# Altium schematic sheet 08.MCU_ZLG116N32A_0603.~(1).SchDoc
size A4; CheckedBy: <审核日期>; Author: 伍伟业; CompanyName: 广州周立功单片机科技有限公司; DocumentNumber: 7; SheetNumber: 7; SheetTotal: 7; PageSetup: Record=PageOptions¦CenterHorizontal=True¦CenterVertical=True¦PrintScale=1.00¦XCorrection=1.00¦YCorrection=1.00¦PrintKind=0¦BorderSize=5000000¦LeftOffset=0¦BottomOffset=0¦Orientation=2¦PaperLength=1000¦PaperWidth=1000¦Scale=100¦PaperSource=7¦PrintQuality=600¦MediaType=1¦DitherType=10¦PaperKind=A4¦PrintScaleMode=1; DesignDate: 2016-8-4; CheckDate: 赵金生; SheetName: MCU_ZLG116N32A; SheetVersion: Rev.A; SheetDescription: ZLG116N32A最小系统
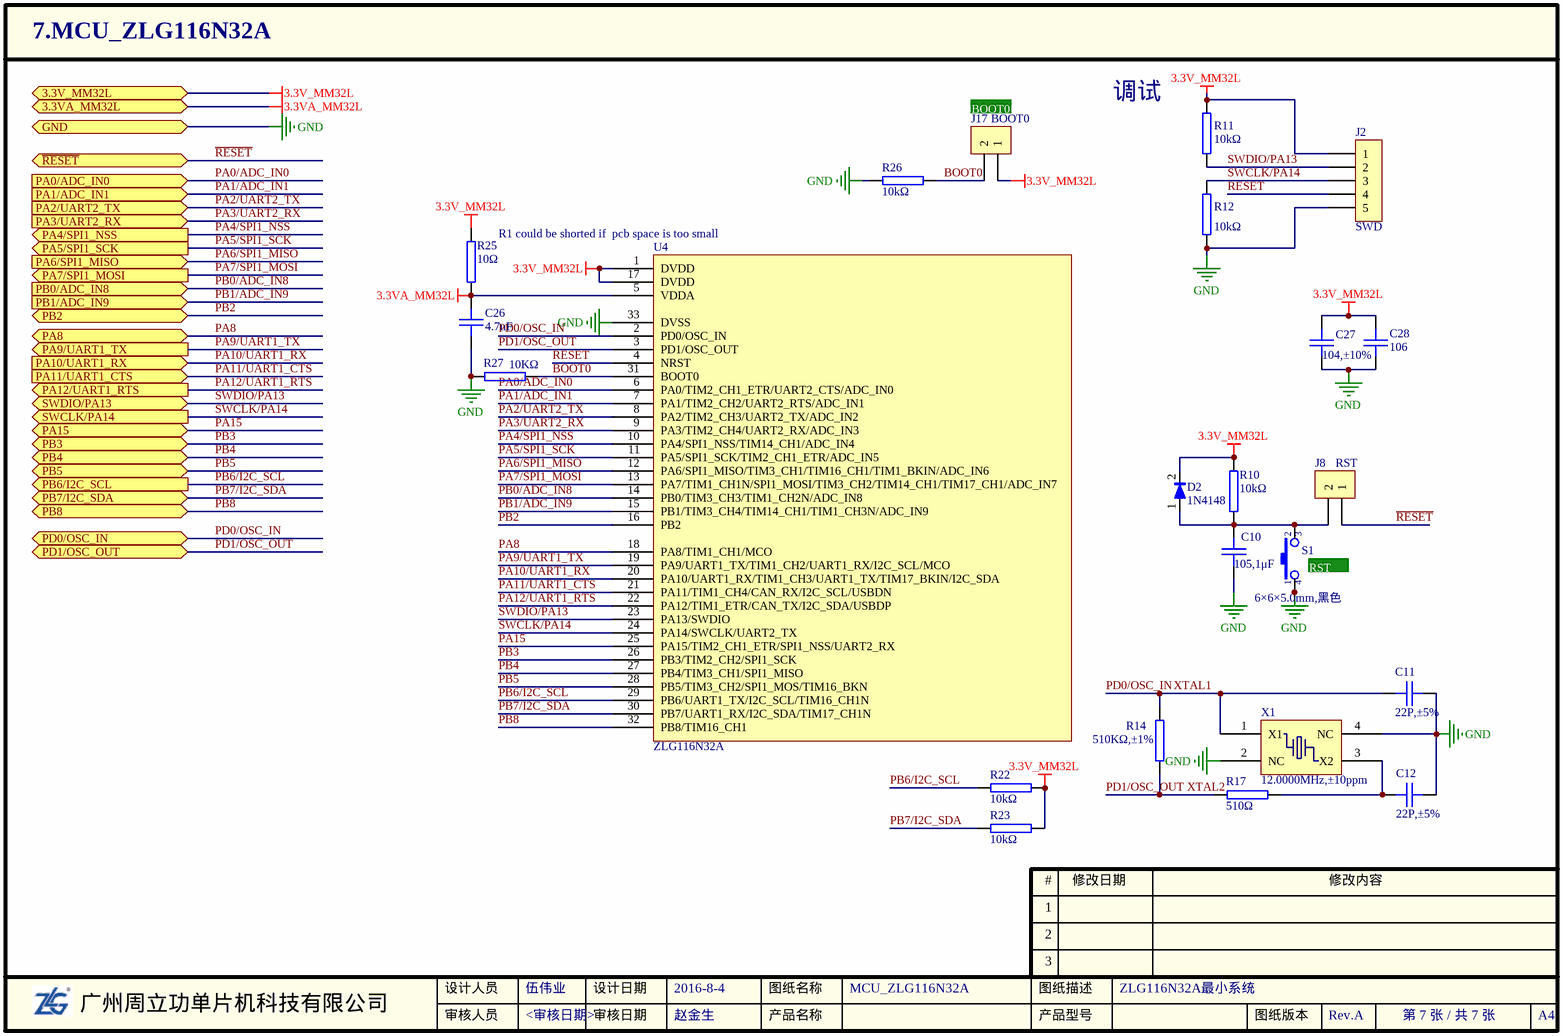
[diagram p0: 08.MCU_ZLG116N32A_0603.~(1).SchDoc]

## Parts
C10  105,1μF  [0603C]
C11  22P,±5%  [0603C]
C12  22P,±5%  [0603C]
C26  4.7uF  [0603C]
C27  104,±10%  [0603C]
C28  106  [0805C]
D2  value 1N4148  [SOD-323]  (hidden comment: DIODE1)
J2  SWD  [SIP-5-2.54-R90]
J8  RST  [SIP-2-2.54]
J17  BOOT0  [SIP-2-2.54]
R10  10kΩ  [0603R]
R11  10kΩ  [0603R]
R12  10kΩ  [0603R]
R14  510KΩ,±1%  [禁止选用0603R]
R17  510Ω  [0603R]
R22  10kΩ  [0603R]
R23  10kΩ  [0603R]
R25  10Ω  [0603R]
R26  10kΩ  [0603R]
R27  10KΩ  [0603R]
S1  value 6×6×5.0mm,黑色  [KEY-6S]  (hidden comment: RST)
U4  ZLG116N32A  [QFN50P500X500X85-33N]
X1  12.0000MHz,±10ppm  [XTAL4-3.2X2.5]

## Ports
3.3V_MM32L, 3.3VA_MM32L, GND, PA0/ADC_IN0 (in), PA1/ADC_IN1 (in), PA2/UART2_TX (in), PA3/UART2_RX (in), PA4/SPI1_NSS (out), PA5/SPI1_SCK (out), PA6/SPI1_MISO (in), PA7/SPI1_MOSI (out), PA8 (bidir), PA9/UART1_TX (out), PA10/UART1_RX (in), PA11/UART1_CTS (in), PA12/UART1_RTS (out), PA15 (bidir), PB0/ADC_IN8 (in), PB1/ADC_IN9 (in), PB2 (bidir), PB3 (bidir), PB4 (bidir), PB5 (bidir), PB6/I2C_SCL (out), PB7/I2C_SDA (bidir), PB8 (bidir), PD0/OSC_IN (bidir), PD1/OSC_OUT (bidir), SWCLK/PA14 (out), SWDIO/PA13 (bidir), ~{RESET} (bidir)

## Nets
3.3V_MM32L: C27.1 C28.1 D2.2 J2.1 J17.1 R10.2 R11.2 R22.2 R23.2 R25.2 U4.1(DVDD) U4.17(DVDD) ; port 3.3V_MM32L
3.3VA_MM32L: C26.1 R25.1 U4.5(VDDA) ; port 3.3VA_MM32L
GND: C10.2 C11.2 C12.2 C26.2 C27.2 C28.2 J2.5 R12.1 R26.1 R27.1 S1.1 S1.4 U4.33(DVSS) X1.2(NC) X1.4(NC) ; port GND
BOOT0: J17.2 R26.2 R27.2 U4.31(BOOT0)
PA0/ADC_IN0: U4.6(PA0/TIM2_CH1_ETR/UART2_CTS/ADC_IN0) ; port PA0/ADC_IN0
PA1/ADC_IN1: U4.7(PA1/TIM2_CH2/UART2_RTS/ADC_IN1) ; port PA1/ADC_IN1
PA2/UART2_TX: U4.8(PA2/TIM2_CH3/UART2_TX/ADC_IN2) ; port PA2/UART2_TX
PA3/UART2_RX: U4.9(PA3/TIM2_CH4/UART2_RX/ADC_IN3) ; port PA3/UART2_RX
PA4/SPI1_NSS: U4.10(PA4/SPI1_NSS/TIM14_CH1/ADC_IN4) ; port PA4/SPI1_NSS
PA5/SPI1_SCK: U4.11(PA5/SPI1_SCK/TIM2_CH1_ETR/ADC_IN5) ; port PA5/SPI1_SCK
PA6/SPI1_MISO: U4.12(PA6/SPI1_MISO/TIM3_CH1/TIM16_CH1/TIM1_BKIN/ADC_IN6) ; port PA6/SPI1_MISO
PA7/SPI1_MOSI: U4.13(PA7/TIM1_CH1N/SPI1_MOSI/TIM3_CH2/TIM14_CH1/TIM17_CH1/ADC_IN7) ; port PA7/SPI1_MOSI
PA8: U4.18(PA8/TIM1_CH1/MCO) ; port PA8
PA9/UART1_TX: U4.19(PA9/UART1_TX/TIM1_CH2/UART1_RX/I2C_SCL/MCO) ; port PA9/UART1_TX
PA10/UART1_RX: U4.20(PA10/UART1_RX/TIM1_CH3/UART1_TX/TIM17_BKIN/I2C_SDA) ; port PA10/UART1_RX
PA11/UART1_CTS: U4.21(PA11/TIM1_CH4/CAN_RX/I2C_SCL/USBDN) ; port PA11/UART1_CTS
PA12/UART1_RTS: U4.22(PA12/TIM1_ETR/CAN_TX/I2C_SDA/USBDP) ; port PA12/UART1_RTS
PA15: U4.25(PA15/TIM2_CH1_ETR/SPI1_NSS/UART2_RX) ; port PA15
PB0/ADC_IN8: U4.14(PB0/TIM3_CH3/TIM1_CH2N/ADC_IN8) ; port PB0/ADC_IN8
PB1/ADC_IN9: U4.15(PB1/TIM3_CH4/TIM14_CH1/TIM1_CH3N/ADC_IN9) ; port PB1/ADC_IN9
PB2: U4.16(PB2) ; port PB2
PB3: U4.26(PB3/TIM2_CH2/SPI1_SCK) ; port PB3
PB4: U4.27(PB4/TIM3_CH1/SPI1_MISO) ; port PB4
PB5: U4.28(PB5/TIM3_CH2/SPI1_MOS/TIM16_BKN) ; port PB5
PB6/I2C_SCL: R22.1 U4.29(PB6/UART1_TX/I2C_SCL/TIM16_CH1N) ; port PB6/I2C_SCL
PB7/I2C_SDA: R23.1 U4.30(PB7/UART1_RX/I2C_SDA/TIM17_CH1N) ; port PB7/I2C_SDA
PB8: U4.32(PB8/TIM16_CH1) ; port PB8
PD0/OSC_IN: C11.1 R14.2 U4.2(PD0/OSC_IN) X1.1(X1) ; port PD0/OSC_IN  [also labelled XTAL1]
PD1/OSC_OUT: R14.1 R17.1 U4.3(PD1/OSC_OUT) ; port PD1/OSC_OUT  [also labelled XTAL2]
~{RESET}: J2.4 J8.1 U4.4(NRST) ; port ~{RESET}
SWCLK/PA14: J2.3 R12.2 U4.24(PA14/SWCLK/UART2_TX) ; port SWCLK/PA14
SWDIO/PA13: J2.2 R11.1 U4.23(PA13/SWDIO) ; port SWDIO/PA13
NetC10_1: C10.1 D2.1 J8.2 R10.1 S1.2 S1.3
NetC12_1: C12.1 R17.2 X1.3(X2)

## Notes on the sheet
- (near J17) BOOT0
- 调试
- R1 could be shorted if  pcb space is too small
- (near S1) RST

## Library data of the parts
C10 = 1.02.01.0036: 105,1μF,±10%,16V,X7R,0603,*,RoHS; 名称: 电容; 封装: 0603; 厂商: TDK; 贴片和直插: SMT; 器件优选方案: 正常状态，可以选用; 设备封装名称: C0603_105_X7R_16V_10%
C11 C12 = 1.02.01.0005: 22P,±5%,50V,COG,0603,*,RoHS; 名称: 电容; 封装: 0603; 设备封装名称: C0603_22P_COG_50V_5%; 厂商: muRata; 贴片和直插: SMT; 器件优选方案: 临时/偏门物料/不主推物料，谨慎选用
C26 = 1.02.01.0080: GRM188R61A475KE15D,4.7uF,±10%,10V,X5R,0603,muRata,RoHS; 名称: 电容; 封装: 0603; 贴片和直插: SMT; PCB备注: 160602yjh; 器件优选方案: 正常状态，可以选用
C27 = 1.02.01.0032: 104,±10%,50V,X7R,0603,*,RoHS; 名称: 电容; 封装: 0603; 设备封装名称: C0603_104_X7R_50V_10%; 厂商: muRata; 贴片和直插: SMT; 器件优选方案: 量产物料,优先选用
C28 = 1.02.02.0055: 106,10μF,±10%,10V,X5R,0805,RoHS; 名称: 电容; 封装: 0805; 贴片和直插: SMT; 器件优选方案: 量产物料,优先选用; 设备封装名称: C0805_106_X5R_10V_10%
D2 = 1.04.07.0027: 1N4148,SOD-323,RoHS; 名称: 二极管; 设备封装名称: SOD-323_1N4148; 贴片和直插: SMT
J2 = CON5: Connector
J8 J17 = CON2: Connector
R10-R12 R22 R23 R26 = 1.01.01.0052: 10KΩ,±1%,0603,*,RoHS; 名称: 电阻; 封装: 0603; 设备封装名称: R0603_10K_1%; 厂商: Ralec; 贴片和直插: SMT
R14 = 1.01.01.0196: 510KΩ,±1%,0603,RoHS; 名称: 电阻; 封装: 0603; 厂商: Ralec; 贴片和直插: SMT; 器件优选方案: 停产/问题，禁止选用
R17 = 1.01.01.0033: 510Ω,0603,*,RoHS; 名称: 电阻; 封装: 0603; 设备封装名称: R0603_510R; 厂商: Ralec; 贴片和直插: SMT; 器件优选方案: 正常状态，可以选用
R25 = 1.01.01.0007: 10Ω,0603,*,RoHS; 名称: 电阻; 封装: 0603; 设备封装名称: R0603_10R; 厂商: Ralec; 贴片和直插: SMT; 器件优选方案: 正常状态，可以选用
R27 = 1.01.01.0051: 10KΩ,0603,*,RoHS; 名称: 电阻; 封装: 0603; 设备封装名称: R0603_10K; 厂商: Ralec; 贴片和直插: SMT; 器件优选方案: 正常状态，可以选用
S1 = 1.09.01.0003: 6×6×5.0mm,黑色,SMD,,*; 名称: 轻触按键; 贴片和直插: SMT
U4 = 1.05.01.0128: ZLG116N32A,QFN-32,ZLG,RoHs; 名称: 集成电路; 贴片和直插: SMT; PCB备注: 170810CZY; 器件优选方案: 正常状态，可以选用
X1 = 1.07.01.0032: 12.0000MHz,±10ppm,10pF,-40~85℃,±10ppm,SMD3225,*,JYEG,RoHS; 名称: 晶体; 贴片和直插: SMT; PCB备注: 151229lmd; 器件优选方案: 正常状态，可以选用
